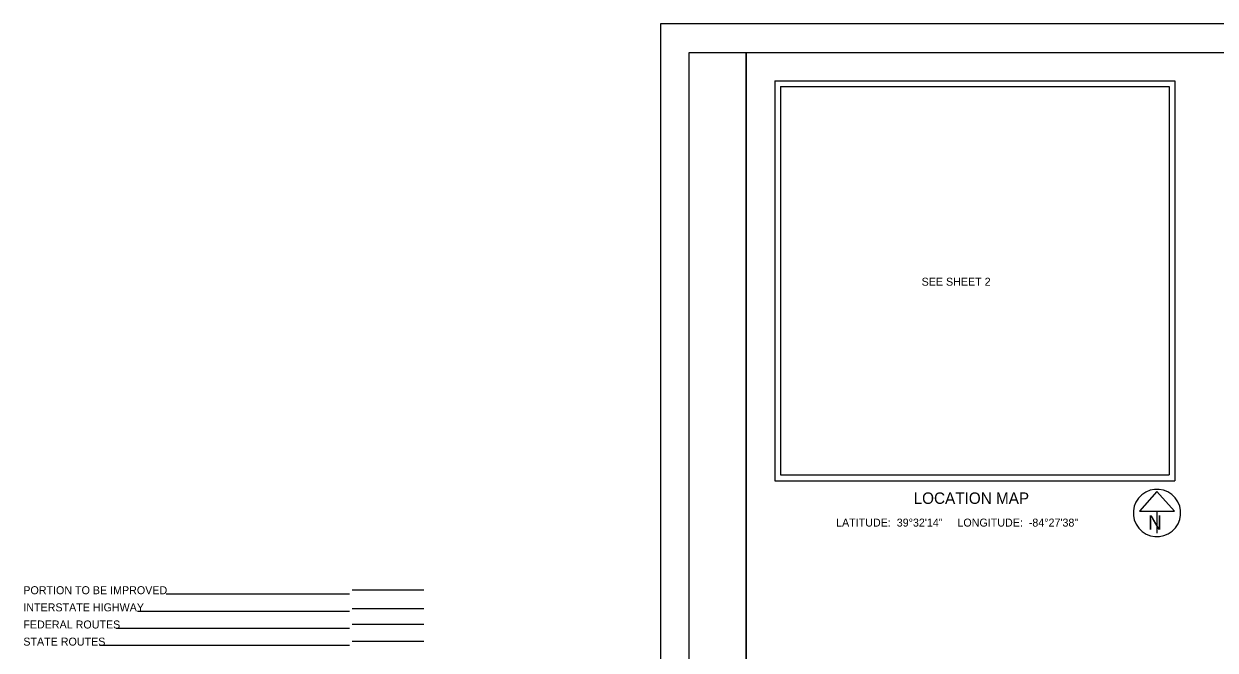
# Model space of a CAD drawing. Extents: x -11.1 to 43.5, y 0 to 22.
# Drawn here: x -11.14 to 9.7, y 11.03 to 22 of the extents above; entities that cross this region are included whole.
import ezdxf

# ---------------------------------------------------------------- set-up
doc = ezdxf.new("R2010")
doc.units = 0
for name, color, linetype in [('SH_Border', 7, 'Continuous'), ('SH_Cut_Line', 7, 'Continuous'), ('SH_Data', 7, 'Continuous'), ('SH_Text', 7, 'Continuous')]:
    doc.layers.add(name, color=color, linetype=linetype)

msp = doc.modelspace()

# ---------------------------------------------------------------- linework, layer by layer
at = {"layer": 'SH_Border'}
for points in [[(0.5, 21.5), (1.5, 21.5), (1.5, 0.5), (0.5, 0.5)], [(1.5, 21.5), (33.5, 21.5), (33.5, 0.5), (1.5, 0.5)]]:
    msp.add_lwpolyline(points, close=True, dxfattribs=at)
at = {"layer": 'SH_Cut_Line'}
msp.add_lwpolyline([(0, 0), (34, 0), (34, 22), (0, 22)], close=True, dxfattribs=at)
at = {"layer": 'SH_Data'}
for p, q in [((2, 21), (9, 21)), ((2, 21), (2, 14)), ((2.1, 20.9), (2.1, 14.1)), ((2.1, 20.9), (8.9, 20.9)), ((8.9, 20.9), (8.9, 14.1)), ((9, 21), (9, 14)), ((2, 14), (9, 14)), ((2.1, 14.1), (8.9, 14.1)), ((2.1, 14.1), (2.1, 14.1)), ((8.685, 13.809), (8.377, 13.468)), ((8.992, 13.468), (8.685, 13.809)), ((8.377, 13.468), (8.992, 13.468)), ((8.685, 13.468), (8.685, 13.081)), ((8.685, 13.435), (8.685, 13.435)), ((8.685, 13.435), (8.685, 13.435)), ((-5.394, 12.091), (-4.144, 12.091)), ((-5.444, 12.012), (-8.65, 12.012)), ((-5.444, 11.712), (-9.155, 11.712)), ((-4.144, 11.756), (-5.394, 11.756)), ((-4.144, 11.484), (-5.394, 11.484)), ((-5.444, 11.412), (-9.525, 11.412)), ((-5.444, 11.112), (-9.815, 11.112)), ((-4.144, 11.184), (-5.394, 11.184))]:
    msp.add_line(p, q, dxfattribs=at)
msp.add_arc((8.685, 13.435), 0.415, 129.7798, 129.7633, dxfattribs=at)

# ---------------------------------------------------------------- texts
msp.add_text('N', height=0.25, dxfattribs=at).set_placement((8.529, 13.144))
at = {"layer": 'SH_Text'}
for s, height, p in [('SEE SHEET 2', 0.14, (4.567, 17.414)), ('LOCATION MAP', 0.2, (4.427, 13.594)), ('LATITUDE:  39°32\'14"     LONGITUDE:  -84°27\'38"', 0.14, (3.071, 13.196)), ('PORTION TO BE IMPROVED', 0.14, (-11.15, 12.012)), ('INTERSTATE HIGHWAY', 0.14, (-11.15, 11.712)), ('FEDERAL ROUTES', 0.14, (-11.15, 11.412)), ('STATE ROUTES', 0.14, (-11.15, 11.112))]:
    msp.add_text(s, height=height, dxfattribs=at).set_placement(p)

doc.saveas('drawing.dxf')
